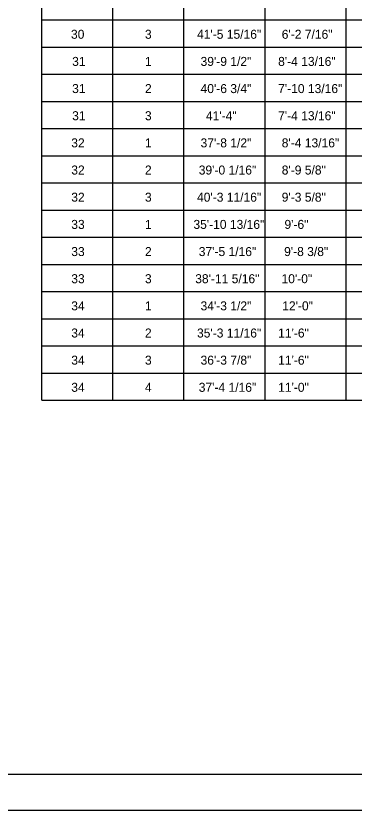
# Model space of a CAD drawing. Extents: x -133.1 to -97, y -1.7 to 20.3.
# Drawn here: x -115.84 to -111.15, y -1.69 to 9.34 of the extents above; entities that cross this region are included whole.
import ezdxf

# ---------------------------------------------------------------- set-up
doc = ezdxf.new("R2010")
doc.units = 0
for name, color, linetype in [('BR_BORDER LINES', 7, 'Continuous'), ('BR_TABLE LINES', 7, 'Continuous'), ('BR_TEXT', 7, 'Continuous'), ('Level 31', 7, 'Continuous')]:
    doc.layers.add(name, color=color, linetype=linetype)

msp = doc.modelspace()

# ---------------------------------------------------------------- linework, layer by layer
at = {"layer": 'BR_BORDER LINES'}
msp.add_line((-131.308, -1.191), (-97.642, -1.191), dxfattribs=at)
at = {"layer": 'BR_TABLE LINES'}
for p, q in [((-115.482, 4.001), (-115.482, 19.253)), ((-114.497, 4.001), (-114.497, 18.753)), ((-113.512, 4.001), (-113.512, 18.753)), ((-112.387, 4.001), (-112.387, 18.753)), ((-111.262, 4.001), (-111.262, 18.753)), ((-115.482, 9.28), (-103.387, 9.28)), ((-115.482, 8.903), (-103.387, 8.903)), ((-115.482, 8.526), (-103.387, 8.526)), ((-115.482, 8.148), (-103.387, 8.148)), ((-115.482, 7.771), (-103.387, 7.771)), ((-115.482, 7.394), (-103.387, 7.394)), ((-115.482, 7.017), (-103.387, 7.017)), ((-115.482, 6.64), (-103.387, 6.64)), ((-115.482, 6.263), (-103.387, 6.263)), ((-115.482, 5.886), (-103.387, 5.886)), ((-115.482, 5.509), (-103.387, 5.509)), ((-115.482, 5.132), (-103.387, 5.132)), ((-115.482, 4.755), (-103.387, 4.755)), ((-115.482, 4.378), (-103.387, 4.378)), ((-115.482, 4.001), (-103.387, 4.001))]:
    msp.add_line(p, q, dxfattribs=at)
at = {"layer": 'Level 31'}
msp.add_lwpolyline([(-133.141, -1.691), (-97.141, -1.691), (-97.141, 20.309), (-133.141, 20.309)], close=True, dxfattribs=at)

# ---------------------------------------------------------------- texts
at = {"layer": 'BR_TEXT'}
for s, p in [('30', (-115.079, 9.019)), ('3', (-114.053, 9.019)), ('41\'-5 15/16"', (-113.331, 9.019)), ('6\'-2 7/16"', (-112.156, 9.019)), ('31', (-115.063, 8.642)), ('1', (-114.053, 8.642)), ('39\'-9 1/2"', (-113.282, 8.642)), ('8\'-4 13/16"', (-112.206, 8.642)), ('31', (-115.063, 8.265)), ('2', (-114.053, 8.265)), ('40\'-6 3/4"', (-113.282, 8.265)), ('7\'-10 13/16"', (-112.206, 8.265)), ('31', (-115.063, 7.888)), ('3', (-114.053, 7.888)), ('41\'-4"', (-113.207, 7.888)), ('7\'-4 13/16"', (-112.206, 7.888)), ('32', (-115.075, 7.511)), ('1', (-114.053, 7.511)), ('37\'-8 1/2"', (-113.282, 7.511)), ('8\'-4 13/16"', (-112.156, 7.511)), ('32', (-115.075, 7.134)), ('2', (-114.053, 7.134)), ('39\'-0 1/16"', (-113.307, 7.134)), ('8\'-9 5/8"', (-112.156, 7.134)), ('32', (-115.075, 6.757)), ('3', (-114.053, 6.757)), ('40\'-3 11/16"', (-113.331, 6.757)), ('9\'-3 5/8"', (-112.156, 6.757)), ('35\'-10 13/16"', (-113.381, 6.379)), ('33', (-115.075, 6.379)), ('1', (-114.053, 6.379)), ('9\'-6"', (-112.118, 6.379)), ('33', (-115.075, 6.002)), ('2', (-114.053, 6.002)), ('37\'-5 1/16"', (-113.307, 6.002)), ('9\'-8 3/8"', (-112.123, 6.002)), ('33', (-115.075, 5.625)), ('3', (-114.053, 5.625)), ('38\'-11 5/16"', (-113.356, 5.625)), ('10\'-0"', (-112.159, 5.625)), ('34', (-115.075, 5.248)), ('1', (-114.053, 5.248)), ('34\'-3 1/2"', (-113.282, 5.248)), ('12\'-0"', (-112.149, 5.248)), ('34', (-115.075, 4.871)), ('2', (-114.053, 4.871)), ('35\'-3 11/16"', (-113.331, 4.871)), ('11\'-6"', (-112.206, 4.871)), ('34', (-115.075, 4.494)), ('3', (-114.053, 4.494)), ('36\'-3 7/8"', (-113.282, 4.494)), ('11\'-6"', (-112.206, 4.494)), ('34', (-115.075, 4.117)), ('4', (-114.053, 4.117)), ('37\'-4 1/16"', (-113.307, 4.117)), ('11\'-0"', (-112.206, 4.117))]:
    msp.add_text(s, height=0.125, rotation=360, dxfattribs=at).set_placement(p)

doc.saveas('drawing.dxf')
